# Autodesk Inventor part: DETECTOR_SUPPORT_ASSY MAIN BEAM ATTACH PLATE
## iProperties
Shininess: 64.0
Length Units: 11272
Angle Units: 11279
Time Units: 11290
Mass Units: 11286
Length Display Precision: 3
Angle Display Precision: 2
Compacted: True
Part Number: DETECTOR_SUPPORT_ASSY MAIN BEAM ATTACH PLATE
Document SubType Name: Modeling
Created: 2004-08
Designer: John Blackburn
Material: MILD_STEEL
Manufacturer: Standard
Standards Organization: Custom
Density: 0.0
Volumn: 0.0
Area: 0.0
PropertySet Name: Model Information
Control State: 0
Master: False
Checked Out: False
Author: John Blackburn
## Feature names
1. ExtrusionMidplane1
2. ExtrusionBlind1
3. ExtrusionThru2
4. AM_HOLE_SI0030_1 [Hole]
5. Rectangular Pattern1
